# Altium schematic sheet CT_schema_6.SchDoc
size 278 x 170 mm
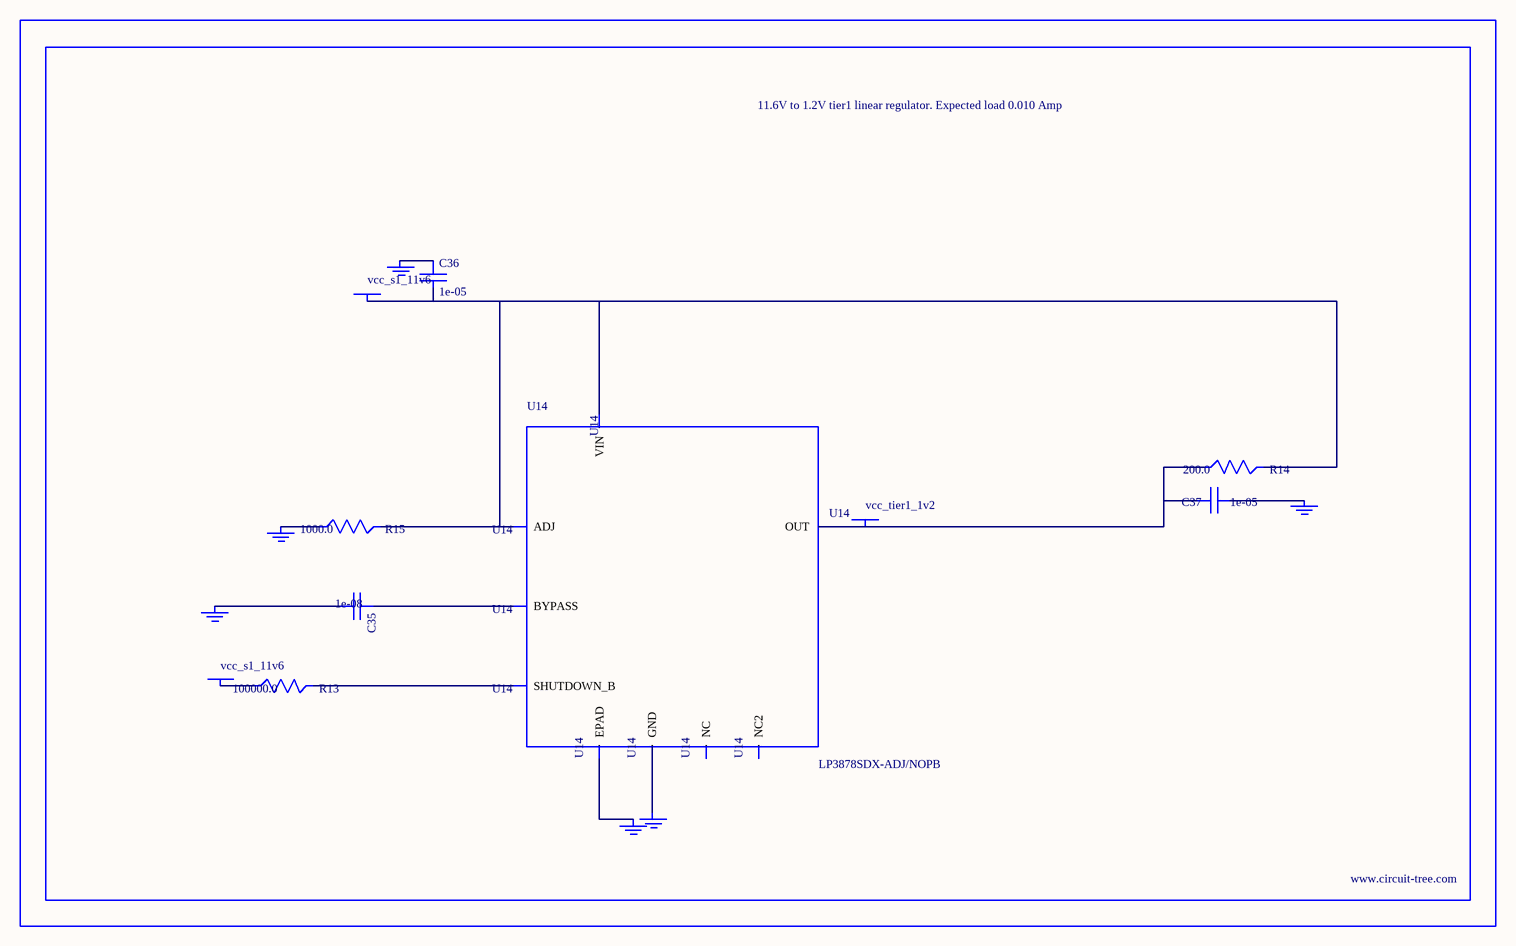
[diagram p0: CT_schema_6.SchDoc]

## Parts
BORDER5  (no value)
C35  1e-08  [C0402]
C36  1e-05  [C1210]
C37  1e-05  [C0805]
GND_INSTANCE_5_0  (no value)
GND_INSTANCE_5_1  (no value)
GND_INSTANCE_5_2  (no value)
GND_INSTANCE_5_3  (no value)
GND_INSTANCE_5_4  (no value)
GND_INSTANCE_5_5  (no value)
POWER_INSTANCE_5_0  vcc_s1_11v6
POWER_INSTANCE_5_1  vcc_s1_11v6
POWER_INSTANCE_5_2  vcc_tier1_1v2
R13  100000.0  [R0603]
R14  200.0  [R0603]
R15  1000.0  [R0603]
U14  LP3878SDX-ADJ/NOPB  [WSON-8]

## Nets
NetC35_1: C35.1 U14.1(BYPASS)
NetC35_2: C35.2 GND_INSTANCE_5_0.0(GND)
NetC36_1: C36.1 GND_INSTANCE_5_1.0(GND)
NetC36_2: C36.2 POWER_INSTANCE_5_0.0(PWR) R14.2 R15.2 U14.4(VIN) U14.6(ADJ)
NetC37_1: C37.1 GND_INSTANCE_5_2.0(GND)
NetC37_2: C37.2 POWER_INSTANCE_5_2.0(PWR) R14.1 U14.5(OUT)
NetGND_INSTANCE_5_3_0: GND_INSTANCE_5_3.0(GND) R15.1
NetGND_INSTANCE_5_4_0: GND_INSTANCE_5_4.0(GND) U14.PAD(EPAD)
NetGND_INSTANCE_5_5_0: GND_INSTANCE_5_5.0(GND) U14.3(GND)
NetPOWER_INSTANCE_5_1_0: POWER_INSTANCE_5_1.0(PWR) R13.1
NetR13_2: R13.2 U14.8(SHUTDOWN_B)

Not connected (* = marked no-connect by the designer): U14 2(NC) 7(NC2)

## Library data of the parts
BORDER5 = BORDER_PAGE5
C35 = C0402C103K3RAC
C36 = C1210C106K5PACTU
C37 = GRM219R60J106ME19D
GND_INSTANCE_5_0-GND_INSTANCE_5_5 = GND
POWER_INSTANCE_5_0-POWER_INSTANCE_5_2 = PWR
R13 = RC0603JR-07100KL
R14 = RC0603JR-07200RL
R15 = RC0603JR-071KL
